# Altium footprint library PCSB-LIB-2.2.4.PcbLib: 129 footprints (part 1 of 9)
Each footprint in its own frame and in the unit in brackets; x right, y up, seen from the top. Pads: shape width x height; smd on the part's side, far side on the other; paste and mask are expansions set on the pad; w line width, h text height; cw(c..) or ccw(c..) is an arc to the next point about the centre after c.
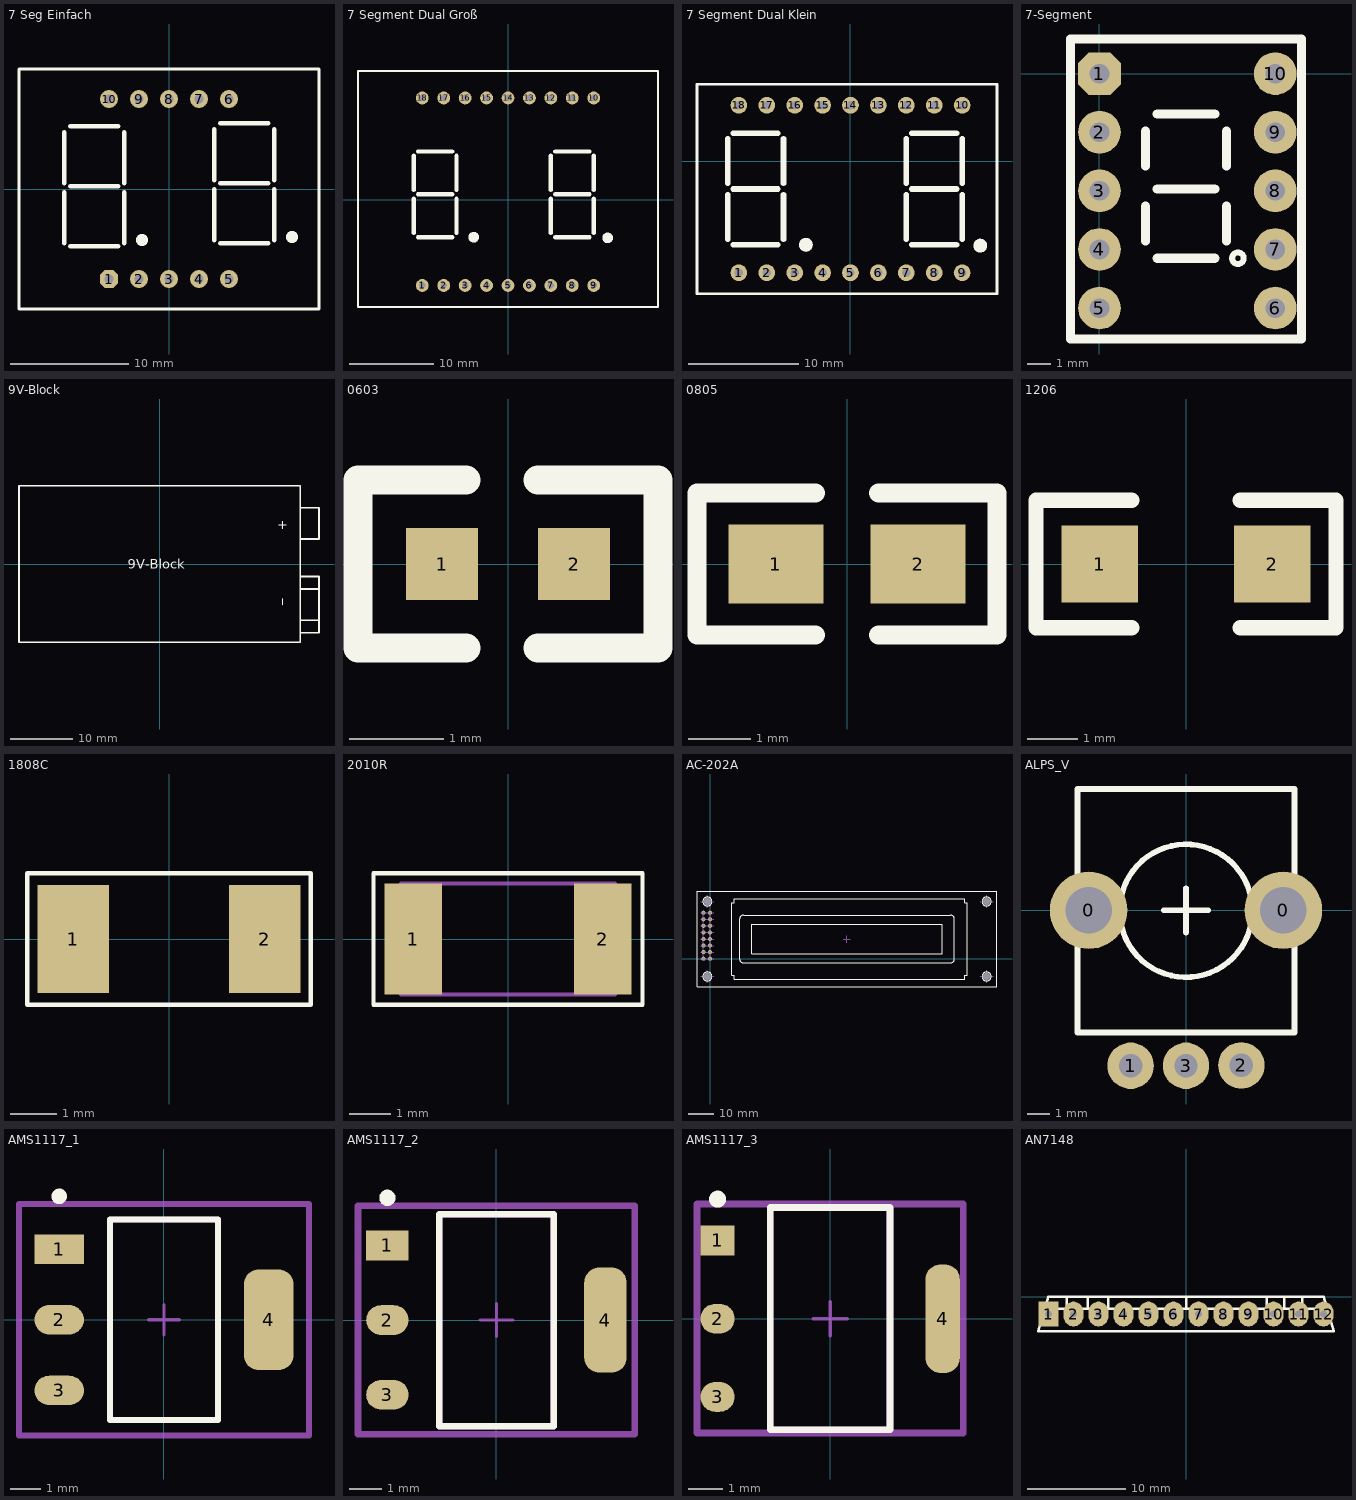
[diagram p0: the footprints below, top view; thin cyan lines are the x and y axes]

## 7 Seg Einfach [mil]
pads (10):
  oct 60x60 hole 30: 1(-200,-300)
  round 60 hole 30: 2(-100,-300) 3(0,-300) 4(100,-300) 5(200,-300) 6(200,300) 7(100,300) 8(0,300) 9(-100,300) 10(-200,300)
Top Overlay:
  circle w20: c-90,-170 r10
  circle w20: c410,-160 r10
  lines w10: 0,400 500,400 ; 500,400 -500,400 -500,-400 500,-400 500,400
  lines w15: -350,-180 -350,-10 ; -350,20 -350,190 ; -330,-190 -170,-190 ; -330,10 -170,10 ; -330,210 -170,210 ; -150,-180 -150,-10 ; -150,20 -150,190 ; 150,-170 150,0 ; 150,30 150,200 ; 170,-180 330,-180 ; 170,20 330,20 ; 170,220 330,220 ; 350,-170 350,0 ; 350,30 350,200

## 7 Segment Dual Groß [mil]
pads (18):
  round 60 hole 30: 1(-400,-400) 2(-300,-400) 3(-200,-400) 4(-100,-400) 5(0,-400) 6(100,-400) 7(200,-400) 8(300,-400) 9(400,-400) 10(400,475) 11(300,475) 12(200,475) 13(100,475) 14(0,475) 15(-100,475) 16(-200,475) 17(-300,475) 18(-400,475)
Top Overlay:
  circle w10: c-160,-175 r20
  circle w10: c465,-178 r20
  rectangle: -176,-191 -142,-158
  rectangle: 449,-194 481,-160
  lines w10: -700,-500 -700,600 700,600 700,-500 -700,-500
  lines w20: -440,-155 -440,5 ; -440,45 -440,205 ; -420,-175 -260,-175 ; -420,25 -260,25 ; -420,225 -260,225 ; -240,-155 -240,5 ; -240,45 -240,205 ; 200,-155 200,5 ; 200,45 200,205 ; 220,-175 380,-175 ; 220,25 380,25 ; 220,225 380,225 ; 400,-155 400,5 ; 400,45 400,205

## 7 Segment Dual Klein [mil]
pads (18):
  round 60 hole 30: 1(-400,-400) 2(-300,-400) 3(-200,-400) 4(-100,-400) 5(0,-400) 6(100,-400) 7(200,-400) 8(300,-400) 9(400,-400) 10(400,200) 11(300,200) 12(200,200) 13(100,200) 14(0,200) 15(-100,200) 16(-200,200) 17(-300,200) 18(-400,200)
Top Overlay:
  circle w10: c465,-303 r20
  circle w10: c-160,-300 r20
  rectangle: 449,-319 481,-285
  rectangle: -176,-316 -142,-283
  lines w10: -550,-475 525,-475 525,275 -550,275 -550,-475
  lines w20: -440,-280 -440,-120 ; -440,-80 -440,80 ; -420,-300 -260,-300 ; -420,-100 -260,-100 ; -420,100 -260,100 ; -240,-280 -240,-120 ; -240,-80 -240,80 ; 200,-280 200,-120 ; 200,-80 200,80 ; 220,-300 380,-300 ; 220,-100 380,-100 ; 220,100 380,100 ; 400,-280 400,-120 ; 400,-80 400,80

## 7-Segment [mm]
pads (10):
  oct 1.85x1.85 hole 0.85: 1(0,0)
  round 1.85 hole 0.85: 2(0,-2.54) 3(0,-5.08) 4(0,-7.62) 5(0,-10.16) 6(7.62,-10.16) 7(7.62,-7.62) 8(7.62,-5.08) 9(7.62,-2.54) 10(7.62,0)
Top Overlay:
  circle w0.254: c6,-8 r0.25
  lines w0.4: 2,-7.25 2,-5.75 ; 2,-4 2,-2.5 ; 2.5,-8 5,-8 ; 2.5,-5 5,-5 ; 2.5,-1.75 5,-1.75 ; 5.5,-7.25 5.5,-5.75 ; 5.5,-4 5.5,-2.5 ; -1.25,-11.5 -1.25,1.5 8.75,1.5 8.75,-11.5 -1.25,-11.5

## 9V-Block [mil]
height 669.29
Top Overlay:
  lines w10: 886.22,-432.68 1004.33,-432.68 1004.33,-78.35 886.22,-78.35 ; 886.22,-353.94 1004.33,-353.94 ; 886.22,-157.09 1004.33,-157.09 ; 886.22,157.87 1004.33,157.87 1004.33,354.72 886.22,354.72 ; -885.43,-491.73 886.22,-491.73 886.22,492.52 -885.43,492.52 -885.43,-491.73
  text "9V-Block" at -200,-30 h60
  text "+" at 740,220 h60
  text "_" at 760,-260 h60

## 0603 [mil]
pads (2):
  rect 30x30 smd: 1(-27.5,0) 2(27.5,0)
Top Overlay:
  lines w12: -17.5,-35 -62.5,-35 -62.5,35 -17.5,35 ; 12.5,-35 62.5,-35 62.5,35 12.5,35

## 0805 [mil]
pads (2):
  rect 60x50 smd: 1(-45,0) 2(45,0)
Top Overlay:
  lines w12: -20,-45 -95,-45 -95,45 -20,45 ; 20,-45 95,-45 95,45 20,45

## 1206 [mil]
pads (2):
  rect 60x60 smd: 1(-67.5,0) 2(67.5,0)
Top Overlay:
  lines w12: -42.5,-50 -117.5,-50 -117.5,50 -42.5,50 ; 42.5,-50 117.5,-50 117.5,50 42.5,50

## 1808C [mm] "Chip Capacitor, 2-Leads, Body 4,5x2,0mm, IPC Medium Density"
height 2
pads (2):
  rect 1.55x2.35 smd: 1(-2.075,0) 2(2.075,0)
Top Overlay:
  lines w0.1: -3.075,-1.425 -3.075,1.425 3.075,1.425 3.075,-1.425 -3.075,-1.425

## 2010R [mm] "Chip Resistor, 2-Leads, Body 5.0x2.5mm, IPC Medium Density"
height 0.7
pads (2):
  rect 1.4x2.7 smd: 1(-2.3,0) 2(2.3,0)
Top Overlay:
  lines w0.1: -3.275,-1.6 3.275,-1.6 3.275,1.6 -3.275,1.6 -3.275,-1.6
Mechanical 13:
  lines w0.1: -2.6,-1.35 2.6,-1.35 2.6,1.35 -2.6,1.35 -2.6,-1.35
3D body: height 0.7, standoff 0, extent -2.6,-1.35 2.6,1.35

## AC-202A [mm]
pads (20):
  round 0 hole 3.15: 0(-1.041,-6.883) 0(-1.041,22.123) 0(106.959,-6.883) 0(106.959,22.123)
  round 1.55 hole 1: 1(0,0) 2(-2.54,0) 3(0,2.54) 4(-2.54,2.54) 5(0,5.08) 6(-2.54,5.08) 7(0,7.62) 8(-2.54,7.62) 9(0,10.16) 10(-2.54,10.16) 11(0,12.7) 12(-2.54,12.7) 13(0,15.24) 14(-2.54,15.24) 15(0,17.78) 16(-2.54,17.78)
Top Overlay:
  circle w0.051: c-1.031,-6.887 r1.75
  circle w0.051: c106.969,-6.887 r1.75
  circle w0.051: c106.969,22.113 r1.75
  circle w0.051: c-1.031,22.113 r1.75
  lines w0.254: -5.031,-10.887 -5.031,26.113 ; -5.031,-10.887 -5.031,26.113 ; -5.031,-10.887 110.969,-10.887 ; -5.031,26.113 110.969,26.113 ; -5.031,26.113 110.969,26.113 ; 110.969,-10.887 110.969,26.113 ; 110.969,-10.887 110.969,26.113 ; 8.369,-6.487 9.369,-6.487 9.369,-7.987 98.569,-7.987 98.569,-6.487 99.569,-6.487 99.569,21.713 98.569,21.713 98.569,23.213 9.369,23.213 9.369,21.713 8.369,21.713 8.369,-6.487 ; 11.469,-0.137 ccw(c12.969,-0.137) 12.969,-1.637 92.969,-1.637 ccw(c92.969,-0.137) 94.469,-0.137 94.469,15.363 ccw(c92.969,15.363) 92.969,16.863 12.969,16.863 ccw(c12.969,15.363) 11.469,15.363 11.469,-0.137 ; 16.219,1.863 16.219,13.363 89.719,13.363 89.719,1.863 16.219,1.863
Mechanical 1:
  circle w0.025: c110.969,26.113 r0.013
  circle w0.025: c110.969,-10.887 r0.013
  circle w0.025: c-5.031,-10.887 r0.013
  circle w0.025: c110.969,-10.887 r0.013
  lines w0.051: -3.531,-6.887 1.469,-6.887 ; -3.531,-0.007 1.469,-0.007 ; -3.531,2.533 1.469,2.533 ; -3.531,5.073 1.469,5.073 ; -3.531,7.613 1.469,7.613 ; -3.531,10.153 1.469,10.153 ; -3.531,12.693 1.469,12.693 ; -3.531,15.233 1.469,15.233 ; -3.531,17.773 1.469,17.773 ; -3.531,22.113 1.469,22.113 ; -2.531,-0.007 -2.531,17.773 ; -1.031,-9.387 -1.031,-4.387 ; -1.031,19.613 -1.031,24.613 ; 0.009,-0.007 0.009,17.773 ; 51.537,7.544 54.305,7.518 ; 52.959,6.172 52.959,8.941 ; 104.469,-6.887 109.469,-6.887 ; 104.469,22.113 109.469,22.113 ; 106.969,-9.387 106.969,-4.387 ; 106.969,19.613 106.969,24.613

## ALPS_V [mm]
height 15
pads (5):
  round 3.5 hole 2.1: 0(-4.4,0) 0(4.4,0)
  round 2.1 hole 1.05: 1(-2.5,-7.02) 2(2.5,-7) 3(0,-7.02)
Top Overlay:
  circle w0.254: c0,-0.02 r3
  lines w0.254: -1,0 1,0 ; 0,-1 0,0 0,1 ; -4.9,-5.52 -4.9,5.48 4.9,5.48 4.9,-5.52 -4.9,-5.52

## AMS1117_1 [mm]
pads (4):
  rect 1.604x0.952 smd paste+0 mask+0: 1(-3.395,2.29)
  rrect100% 1.604x0.952 smd paste+0 mask+0: 2(-3.395,0) 3(-3.395,-2.29)
  rrect59% 1.604x3.262 smd paste+0 mask+0: 4(3.395,0)
Top Overlay:
  circle w0.25: c-3.395,4 r0.125
  lines w0.2: -1.753,-3.253 1.753,-3.253 1.753,3.253 -1.753,3.253 -1.753,-3.253
Mechanical 5:
  lines w0.2: -4.697,-3.752 4.697,-3.752 4.697,3.752 -4.697,3.752 -4.697,-3.752
Mechanical 13:
  lines w0.2: -1.753,-3.253 1.753,-3.253 1.753,3.253 -1.753,3.253 -1.753,-3.253
Mechanical 15:
  lines w0.2: -4.697,-3.752 4.697,-3.752 4.697,3.752 -4.697,3.752 -4.697,-3.752
Mechanical 16:
  lines w0.1: -0.5,0 0.5,0 ; 0,-0.5 0,0.5

## AMS1117_2 [mm]
pads (4):
  rect 1.304x0.912 smd paste+0 mask+0: 1(-3.345,2.29)
  rrect100% 1.304x0.912 smd paste+0 mask+0: 2(-3.345,0) 3(-3.345,-2.29)
  rrect70% 1.304x3.222 smd paste+0 mask+0: 4(3.345,0)
Top Overlay:
  circle w0.25: c-3.345,3.75 r0.125
  lines w0.2: -1.753,-3.253 -1.753,3.253 1.753,3.253 1.753,-3.253 -1.753,-3.253
Mechanical 5:
  lines w0.2: -4.247,-3.502 -4.247,3.502 4.247,3.502 4.247,-3.502 -4.247,-3.502
Mechanical 13:
  lines w0.2: -1.753,-3.253 -1.753,3.253 1.753,3.253 1.753,-3.253 -1.753,-3.253
Mechanical 15:
  lines w0.2: -4.247,-3.502 -4.247,3.502 4.247,3.502 4.247,-3.502 -4.247,-3.502
Mechanical 16:
  lines w0.1: -0.5,0 0.5,0 ; 0,-0.5 0,0.5

## AMS1117_3 [mm]
pads (4):
  rect 1.004x0.872 smd paste+0 mask+0: 1(-3.295,2.29)
  rrect100% 1.004x0.872 smd paste+0 mask+0: 2(-3.295,0) 3(-3.295,-2.29)
  rrect87% 1.004x3.182 smd paste+0 mask+0: 4(3.295,0)
Top Overlay:
  circle w0.25: c-3.295,3.5 r0.125
  lines w0.2: -1.753,-3.253 1.753,-3.253 1.753,3.253 -1.753,3.253 -1.753,-3.253
Mechanical 5:
  lines w0.2: -3.897,-3.353 3.897,-3.353 3.897,3.353 -3.897,3.353 -3.897,-3.353
Mechanical 13:
  lines w0.2: -1.753,-3.253 1.753,-3.253 1.753,3.253 -1.753,3.253 -1.753,-3.253
Mechanical 15:
  lines w0.2: -3.897,-3.353 3.897,-3.353 3.897,3.353 -3.897,3.353 -3.897,-3.353
Mechanical 16:
  lines w0.1: -0.5,0 0.5,0 ; 0,-0.5 0,0.5

## AN7148 [mm]
pads (12):
  rect 2x2.54 hole 0.75: 1(-13.97,-1.753)
  oval 2x2.54 hole 0.75: 2(-11.43,-1.753) 3(-8.89,-1.753) 4(-6.35,-1.753) 5(-3.81,-1.753) 6(-1.27,-1.753) 7(1.27,-1.753) 8(3.81,-1.753) 9(6.35,-1.753) 10(8.89,-1.753) 11(11.43,-1.753) 12(13.97,-1.753)
Top Overlay:
  lines w0.254: -14.343,-1.2 14.343,-1.2 ; -12.1,-1.2 -12.1,0 ; -10,-1.2 -10,0 ; -7.9,-1.2 -7.9,0 ; 0,-1.2 0,0 ; 8.2,-1.2 8.2,0 ; 10,-1.2 10,0 ; 11.8,-1.2 11.8,0 ; -15,-3.5 -14,0 14,0 15,-3.5 -15,-3.5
